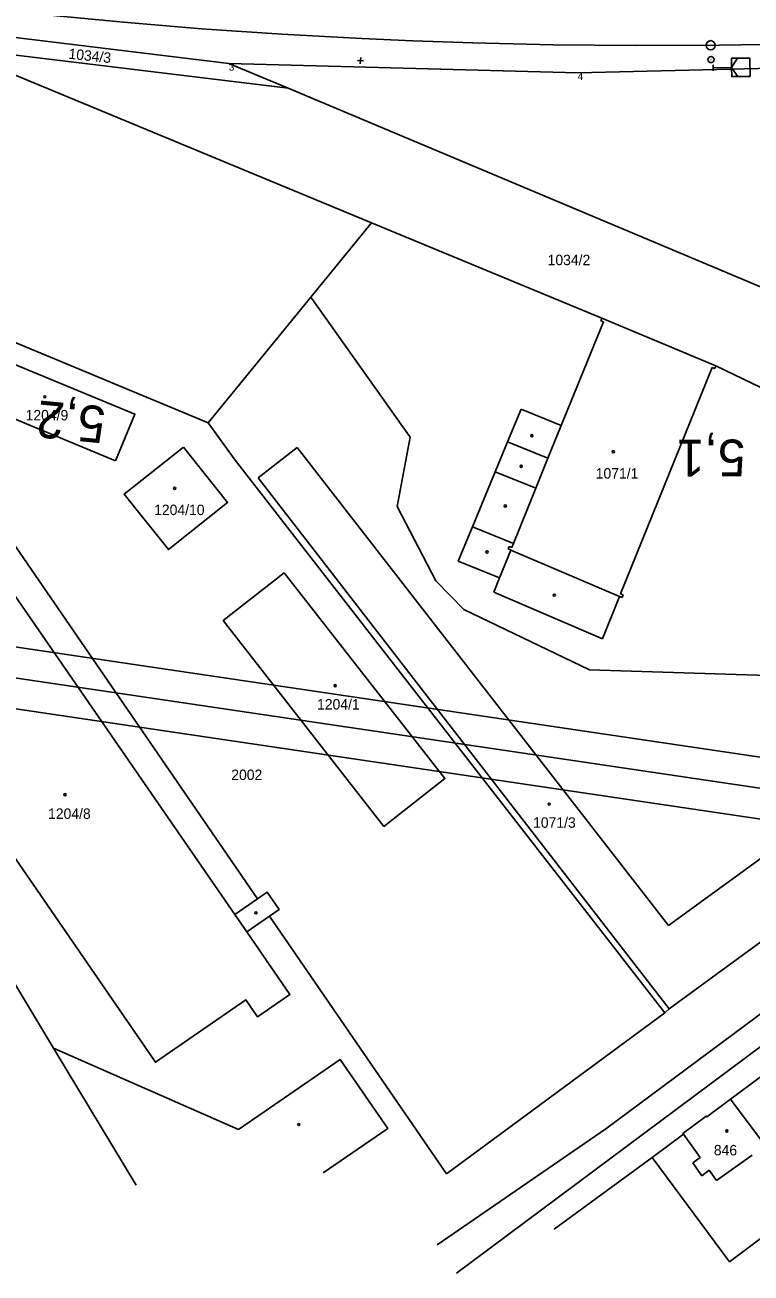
# Model space of a CAD drawing. Extents: x -779330 to -774454, y -1144748 to -1142831.
# Drawn here: x -775422.9 to -775304.5, y -1144665.7 to -1144462.2 of the extents above; entities that cross this region are included whole.
import ezdxf

# ---------------------------------------------------------------- set-up
doc = ezdxf.new("R2010")
doc.units = 0
for name, color, linetype in [('Hranice parcel', 7, 'Continuous'), ('Parcelní čísla', 7, 'Continuous'), ('SŽDC', 7, 'Continuous'), ('Vnitřní kresba', 7, 'Continuous'), ('Vrstva 1', 7, 'Continuous'), ('Vrstva 53', 7, 'Continuous'), ('Vrstva 60', 7, 'Continuous'), ('Vrstva 7', 7, 'Continuous'), ('Značky budov', 7, 'Continuous')]:
    doc.layers.add(name, color=color, linetype=linetype)

msp = doc.modelspace()

# ---------------------------------------------------------------- linework, layer by layer
at = {"layer": 'Hranice parcel'}
for p, q in [((-775380, -1144472.53), (-775435.74, -1144465.74)), ((-775435.74, -1144465.74), (-775366.41, -1144494.44)), ((-775380, -1144472.53), (-775389.68, -1144468.46)), ((-775253.51, -1144525.7), (-775380, -1144472.53)), ((-775366.41, -1144494.44), (-775376.32, -1144506.59)), ((-775393.05, -1144527.1), (-775456.54, -1144500.61)), ((-775456.54, -1144500.61), (-775385.01, -1144604.68)), ((-775376.32, -1144506.59), (-775393.05, -1144527.1)), ((-775383.06, -1144607.52), (-775354.18, -1144649.53)), ((-775318.59, -1144623.31), (-775354.18, -1144649.53)), ((-775294.95, -1144627.78), (-775307.84, -1144637.35)), ((-775418.26, -1144629.06), (-775388.11, -1144642.34)), ((-775404.79, -1144651.38), (-775418.26, -1144629.06)), ((-775320.64, -1144646.86), (-775336.62, -1144658.59)), ((-775320.64, -1144646.86), (-775308.02, -1144663.87))]:
    msp.add_line(p, q, dxfattribs=at)
for points in [[(-775389.68, -1144468.46), (-775425.39, -1144464.15), (-775445.43, -1144461.73)], [(-775204.62, -1144464.16), (-775217.76, -1144465.11), (-775237.91, -1144466.56), (-775289.7, -1144468.96), (-775332.79, -1144469.99), (-775389.68, -1144468.46)], [(-775261.18, -1144541.39), (-775270.96, -1144536.68), (-775294.22, -1144525.5), (-775310.26, -1144517.79), (-775328.85, -1144510.01), (-775366.41, -1144494.44)], [(-775376.32, -1144506.59), (-775360.11, -1144529.4), (-775362.24, -1144540.72), (-775355.95, -1144552.84), (-775351.38, -1144557.51), (-775330.85, -1144567.36), (-775284.69, -1144568.85), (-775263.45, -1144562.01), (-775246.07, -1144570.05)], [(-775408.19, -1144533.28), (-775405.01, -1144525.66), (-775429.35, -1144515.62), (-775432.5, -1144523.14), (-775422.69, -1144527.23), (-775408.19, -1144533.28)], [(-775393.05, -1144527.1), (-775388.65, -1144533.19), (-775318.59, -1144623.31)], [(-775397.1, -1144531.04), (-775406.77, -1144538.71), (-775399.54, -1144547.76), (-775389.9, -1144540.08), (-775397.1, -1144531.04)], [(-775418.26, -1144629.06), (-775432.46, -1144605.51), (-775467.43, -1144547.15)], [(-775385.01, -1144604.68), (-775388.73, -1144607.24), (-775426.16, -1144552.94), (-775441.55, -1144563.53), (-775442.48, -1144562.18), (-775445.69, -1144564.39), (-775444.76, -1144565.75), (-775446.18, -1144566.73), (-775401.66, -1144631.36), (-775386.91, -1144621.19), (-775385.03, -1144623.93), (-775379.73, -1144620.28), (-775386.77, -1144610.08), (-775383.06, -1144607.52)], [(-775364.41, -1144592.92), (-775354.44, -1144585.1), (-775380.64, -1144551.55), (-775390.61, -1144559.33), (-775364.41, -1144592.92)], [(-775318.59, -1144623.31), (-775317.85, -1144622.66), (-775257.86, -1144578.79), (-775246.07, -1144570.05)], [(-775383.06, -1144607.52), (-775381.5, -1144606.44), (-775383.46, -1144603.61), (-775385.01, -1144604.68)], [(-775374.28, -1144649.4), (-775363.74, -1144642.14), (-775371.51, -1144630.92), (-775388.11, -1144642.34)], [(-775307.84, -1144637.35), (-775311.74, -1144640.25), (-775311.83, -1144640.13), (-775315.63, -1144642.95), (-775315.54, -1144643.07), (-775320.64, -1144646.86)], [(-775295.23, -1144654.29), (-775300.12, -1144647.55), (-775302.19, -1144644.93), (-775307.84, -1144637.35)], [(-775308.02, -1144663.87), (-775297.21, -1144655.77), (-775295.23, -1144654.29)]]:
    msp.add_lwpolyline(points, dxfattribs=at)
at = {"layer": 'SŽDC'}
msp.add_lwpolyline([(-775425.39, -1144464.15), (-775389.68, -1144468.46), (-775332.79, -1144469.99), (-775289.7, -1144468.96), (-775237.91, -1144466.56), (-775217.76, -1144465.11), (-775204.62, -1144464.16), (-775201.24, -1144463.92), (-775137.35, -1144459.01), (-775096.64, -1144457.51), (-775076.86, -1144459.23), (-775049.08, -1144458.29), (-775047.73, -1144454.47), (-775006.07, -1144448.84), (-774942.23, -1144444.12), (-774919.16, -1144442.27)], dxfattribs=at)
at = {"layer": 'Vnitřní kresba'}
for p, q in [((-775329.02, -1144510.43), (-775328.85, -1144510.01)), ((-775335.46, -1144527.5), (-775328.6, -1144510.6)), ((-775328.6, -1144510.6), (-775329.02, -1144510.43)), ((-775310.85, -1144518.04), (-775325.78, -1144554.96)), ((-775310.43, -1144518.21), (-775310.85, -1144518.04)), ((-775310.26, -1144517.79), (-775310.43, -1144518.21)), ((-775342.03, -1144524.84), (-775344.23, -1144530.17)), ((-775335.46, -1144527.5), (-775342.03, -1144524.84)), ((-775337.63, -1144532.84), (-775335.46, -1144527.5)), ((-775344.23, -1144530.17), (-775346.26, -1144535.06)), ((-775344.23, -1144530.17), (-775337.63, -1144532.84)), ((-775378.54, -1144531.1), (-775384.93, -1144536.07)), ((-775317.98, -1144609.04), (-775378.54, -1144531.1)), ((-775339.62, -1144537.76), (-775337.63, -1144532.84)), ((-775384.93, -1144536.07), (-775317.85, -1144622.66)), ((-775346.26, -1144535.06), (-775349.97, -1144544.03)), ((-775346.26, -1144535.06), (-775339.62, -1144537.76)), ((-775343.26, -1144546.75), (-775339.62, -1144537.76)), ((-775349.97, -1144544.03), (-775352.28, -1144549.61)), ((-775349.97, -1144544.03), (-775343.26, -1144546.75)), ((-775343.52, -1144547.4), (-775343.26, -1144546.75)), ((-775345.53, -1144552.35), (-775343.69, -1144547.82)), ((-775344.11, -1144547.65), (-775343.94, -1144547.23)), ((-775343.69, -1144547.82), (-775344.11, -1144547.65)), ((-775343.94, -1144547.23), (-775343.52, -1144547.4)), ((-775343.69, -1144547.82), (-775325.95, -1144555.38)), ((-775352.28, -1144549.61), (-775345.53, -1144552.35)), ((-775346.48, -1144554.7), (-775345.53, -1144552.35)), ((-775328.74, -1144562.28), (-775346.48, -1144554.7)), ((-775325.78, -1144554.96), (-775325.36, -1144555.13)), ((-775325.36, -1144555.13), (-775325.53, -1144555.54)), ((-775325.95, -1144555.38), (-775328.74, -1144562.28)), ((-775325.53, -1144555.54), (-775325.95, -1144555.38)), ((-775219.39, -1144566.53), (-775352.58, -1144665.72)), ((-775264.3, -1144570.05), (-775317.98, -1144609.04)), ((-775269.86, -1144598.82), (-775328.21, -1144642.2)), ((-775388.73, -1144607.24), (-775386.77, -1144610.08)), ((-775355.7, -1144661.12), (-775328.21, -1144642.2)), ((-775315.54, -1144643.07), (-775312.81, -1144646.89)), ((-775310.13, -1144650.62), (-775304.35, -1144646.48)), ((-775312.81, -1144646.89), (-775314.03, -1144647.76)), ((-775314.03, -1144647.76), (-775312.55, -1144649.85)), ((-775312.55, -1144649.85), (-775311.32, -1144648.96)), ((-775311.32, -1144648.96), (-775310.13, -1144650.62))]:
    msp.add_line(p, q, dxfattribs=at)
at = {"layer": 'Vrstva 1'}
for points in [[(-774799.29, -1144366.04), (-776045.7, -1144181.56), (-776089.18, -1144475.34), (-774842.77, -1144659.83)], [(-774846.98, -1144654.15), (-776083.5, -1144471.13), (-776041.48, -1144187.23), (-774804.97, -1144370.25)], [(-774810.64, -1144374.46), (-775834.48, -1144222.92), (-775875.04, -1144496.94), (-774851.19, -1144648.48)], [(-774851.19, -1144648.48), (-775875.04, -1144496.94), (-775834.48, -1144222.92), (-774810.64, -1144374.46)]]:
    msp.add_lwpolyline(points, close=True, dxfattribs=at)
msp.add_lwpolyline([(-775237.52, -1144462.13), (-775254.42, -1144463.35), (-775267.45, -1144464.14), (-775280.95, -1144464.78), (-775295.68, -1144465.25), (-775309.68, -1144465.5), (-775323.38, -1144465.56), (-775336.76, -1144465.43), (-775349.91, -1144465.12), (-775359.65, -1144464.79), (-775367.99, -1144464.43), (-775381.03, -1144463.72), (-775394.17, -1144462.83), (-775406.88, -1144461.77), (-775420.1, -1144460.52), (-775432.46, -1144459.19)], dxfattribs=at)
at = {"layer": 'Vrstva 53'}
for points in [[(-774919.16, -1144442.27), (-774942.23, -1144444.12), (-775006.07, -1144448.84), (-775047.73, -1144454.47), (-775049.08, -1144458.29), (-775076.86, -1144459.23), (-775096.64, -1144457.51), (-775137.35, -1144459.01), (-775201.24, -1144463.92), (-775204.62, -1144464.16), (-775217.76, -1144465.11), (-775237.91, -1144466.56), (-775289.7, -1144468.96), (-775332.79, -1144469.99)], [(-774919.16, -1144442.27), (-774942.23, -1144444.12), (-775006.07, -1144448.84), (-775047.73, -1144454.47), (-775049.08, -1144458.29), (-775076.86, -1144459.23), (-775096.64, -1144457.51), (-775137.35, -1144459.01), (-775201.24, -1144463.92), (-775204.62, -1144464.16), (-775217.76, -1144465.11), (-775237.91, -1144466.56), (-775289.7, -1144468.96), (-775332.79, -1144469.99)], [(-775332.79, -1144469.99), (-775389.68, -1144468.46), (-775425.39, -1144464.15)], [(-775332.79, -1144469.99), (-775389.68, -1144468.46), (-775425.39, -1144464.15)]]:
    msp.add_lwpolyline(points, dxfattribs=at)
at = {"layer": 'Vrstva 60'}
for p, q in [((-775389.68, -1144468.46), (-775389.68, -1144468.46)), ((-775332.79, -1144469.99), (-775332.79, -1144469.99))]:
    msp.add_line(p, q, dxfattribs=at)
at = {"layer": 'Vrstva 7'}
for p, q in [((-775368.24, -1144468.53), (-775368.18, -1144467.53)), ((-775367.71, -1144468.05), (-775368.71, -1144468)), ((-775310.99, -1144467.83), (-775311.08, -1144467.84)), ((-775310.7, -1144468.68), (-775310.69, -1144469.68)), ((-775307.7, -1144469.13), (-775310.7, -1144469.18))]:
    msp.add_line(p, q, dxfattribs=at)
for points in [[(-775307.7, -1144469.13), (-775307.67, -1144470.63), (-775304.67, -1144470.59), (-775304.72, -1144467.59), (-775307.72, -1144467.63), (-775307.7, -1144469.13)], [(-775306.72, -1144467.62), (-775307.7, -1144469.13), (-775306.67, -1144470.62)]]:
    msp.add_lwpolyline(points, dxfattribs=at)
for centre, radius in [((-775311.09, -1144465.51), 0.75), ((-775311.04, -1144467.84), 0.5)]:
    msp.add_circle(centre, radius, dxfattribs=at)
at = {"layer": 'Značky budov'}
for centre in [(-775419.7, -1144522.85), (-775340.26, -1144529.17), (-775326.98, -1144531.77), (-775342, -1144534.18), (-775398.53, -1144537.75), (-775344.59, -1144540.64), (-775347.58, -1144548.15), (-775336.6, -1144555.18), (-775372.35, -1144569.93), (-775416.4, -1144587.71), (-775337.43, -1144589.27), (-775385.27, -1144606.99), (-775378.27, -1144641.5), (-775308.46, -1144642.57)]:
    msp.add_circle(centre, 0.175, dxfattribs=at)

# ---------------------------------------------------------------- texts
at = {"layer": 'Parcelní čísla'}
msp.add_text('1034/3', height=1.7, rotation=354, dxfattribs=at).set_placement((-775415.9, -1144467.7))
for s, p in [('1034/2', (-775337.69, -1144501.37)), ('1204/9', (-775422.83, -1144526.68)), ('1071/1', (-775329.84, -1144536.17)), ('1204/10', (-775401.87, -1144542.12)), ('1204/1', (-775375.3, -1144573.83)), ('2002', (-775389.29, -1144585.32)), ('1204/8', (-775419.17, -1144591.66)), ('1071/3', (-775340.06, -1144593.11)), ('846', (-775310.58, -1144646.53))]:
    msp.add_text(s, height=1.7, dxfattribs=at).set_placement(p)
at = {"layer": 'Vrstva 60'}
for s, p in [('3', (-775389.68, -1144469.66)), ('4', (-775332.79, -1144471.19))]:
    msp.add_text(s, height=1.2, dxfattribs=at).set_placement(p)
at = {"layer": 'Vrstva 7'}
for s, rotation, p in [('5,2', 174.6024, (-775409.6, -1144524.47)), ('5,1', 180.2341, (-775305.45, -1144529.8))]:
    msp.add_text(s, height=6, rotation=rotation, dxfattribs=at).set_placement(p)

doc.saveas('drawing.dxf')
